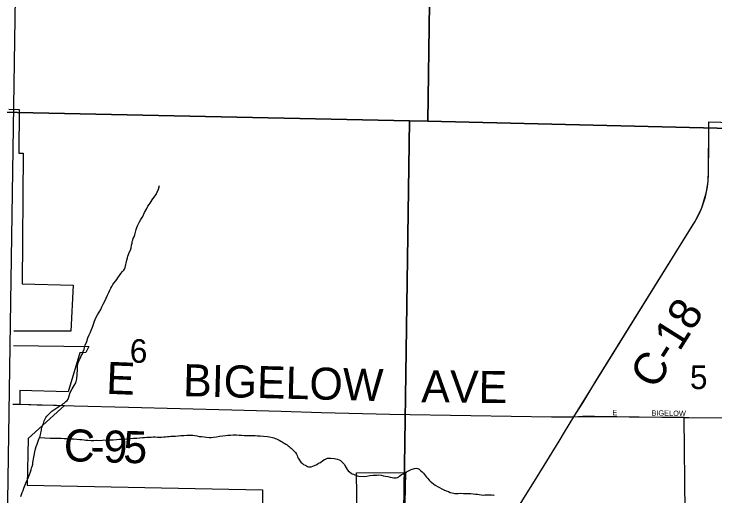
# Model space of a CAD drawing. Extents: x 1587405 to 1714697, y 1028970 to 1155083.
# Drawn here: x 1652641 to 1659199, y 1120584 to 1125096 of the extents above; entities that cross this region are included whole.
import ezdxf

# ---------------------------------------------------------------- set-up
doc = ezdxf.new("R2010")
doc.units = 0
for name, color, linetype in [('GM_X_City_Street', 7, 'Continuous'), ('GM_X_City_Street_Text', 7, 'Continuous'), ('GM_X_Corporation', 7, 'Continuous'), ('GM_X_County_Road', 7, 'Continuous'), ('GM_X_County_Road_Text', 7, 'Continuous'), ('GM_X_Minor_River', 7, 'Continuous'), ('GM_X_Rail_Line', 7, 'Continuous'), ('GM_X_Section', 7, 'Continuous'), ('GM_X_Section_Text', 7, 'Continuous')]:
    doc.layers.add(name, color=color, linetype=linetype)

msp = doc.modelspace()

# ---------------------------------------------------------------- linework, layer by layer
at = {"layer": 'GM_X_City_Street'}
for points in [[(1652630.5, 1121444.8), (1652694.2, 1121443.7)], [(1657877.7, 1121326.3), (1657959.4, 1121330.9), (1658004.6, 1121332.2), (1658071.3, 1121331.8), (1658909.3, 1121318.3)], [(1658909.3, 1121318.3), (1658955.7, 1121317.5), (1659332.4, 1121314.8), (1659921.8, 1121300.5), (1660298.6, 1121295.1), (1660354.3, 1121294.3)]]:
    msp.add_lwpolyline(points, dxfattribs=at)
at = {"layer": 'GM_X_Corporation'}
for points in [[(1652592, 1124205), (1652690.2, 1124200.8), (1652687.2, 1123791.5), (1652725.8, 1123791.5), (1652716.6, 1122570.3), (1653196.1, 1122558.6), (1653173.1, 1122125.9), (1652638.6, 1122126.2)], [(1658937.7, 1118659.7), (1658909.3, 1121318.3), (1657877.6, 1121326.3), (1659011.7, 1123151.3), (1659077, 1123282.1), (1659120.9, 1123430.8), (1659135, 1123527.3), (1659137.3, 1123597.9), (1659142.1, 1124087.2), (1660138.3, 1124058.6)], [(1652636.4, 1121991.9), (1653340.5, 1121983.2), (1653312.4, 1121926.9), (1653256.9, 1121924.1), (1653147.7, 1121558.6), (1652696, 1121572.7), (1652694.2, 1121443.7), (1653113.7, 1121430.9), (1652774.2, 1121120.9), (1652763.2, 1120685.9), (1654964.8, 1120642.1), (1654964.7, 1120391.2)], [(1655850.7, 1120385.1), (1655846.4, 1120801.7), (1656304.6, 1120803.9), (1656274.1, 1119387)]]:
    msp.add_lwpolyline(points, dxfattribs=at)
at = {"layer": 'GM_X_County_Road'}
for points in [[(1657877.7, 1121326.3), (1657961.7, 1121456.5), (1658084.7, 1121657.4), (1658447.7, 1122240.9), (1658930.7, 1123019.5), (1659008, 1123144.8), (1659040.2, 1123201.5), (1659061.8, 1123245.2), (1659080.4, 1123290.2), (1659096.3, 1123336.4), (1659109.9, 1123383.3), (1659120.9, 1123430.8), (1659129.1, 1123478.9), (1659135, 1123527.3), (1659136.7, 1123561.1), (1659137.3, 1123597.9), (1659139.1, 1123680.9), (1659140.8, 1123811.2), (1659142.9, 1123992.6), (1659142.1, 1124087.2)], [(1652694.2, 1121443.7), (1652857.9, 1121438.2), (1653038.6, 1121433.4), (1653113.7, 1121430.9)], [(1653113.7, 1121430.9), (1653202.6, 1121428.1), (1653711.6, 1121414.1), (1654680.3, 1121389.6), (1655140.1, 1121377.7), (1655517.5, 1121366.6), (1656158, 1121350.4), (1656913.4, 1121336.2), (1657669, 1121324.9), (1657793.5, 1121323.8), (1657877.7, 1121326.3)], [(1656896.3, 1119728.3), (1657089, 1120038), (1657268.5, 1120331.6), (1657535, 1120763.9), (1657741.7, 1121098.3), (1657792.5, 1121182.6), (1657877.7, 1121326.3)]]:
    msp.add_lwpolyline(points, dxfattribs=at)
at = {"layer": 'GM_X_Minor_River'}
for points in [[(1652949.7, 1121331.1), (1652962, 1121342.8), (1652972.3, 1121354.7), (1652982.5, 1121366.5), (1652994.8, 1121378.3), (1653015.2, 1121391.9), (1653033.5, 1121403.6), (1653049.8, 1121415.3), (1653064, 1121425), (1653078.2, 1121430.8), (1653088.4, 1121438.6), (1653098.6, 1121446.4), (1653110.8, 1121454.2), (1653125.1, 1121469.9), (1653137.3, 1121477.7), (1653147.6, 1121489.5), (1653167, 1121553.3), (1653183.7, 1121587.1), (1653202.4, 1121616.8), (1653219, 1121642.5), (1653227.8, 1121680.5), (1653232.6, 1121720.5), (1653235.6, 1121768.6), (1653236.2, 1121800.6), (1653238.6, 1121818.7), (1653242.9, 1121830.6), (1653247.2, 1121844.6), (1653253.5, 1121860.5), (1653261.9, 1121878.4), (1653270.3, 1121896.2), (1653280.7, 1121916.1), (1653289.2, 1121936), (1653297.7, 1121957.9), (1653306.5, 1121995.8), (1653321.2, 1122029.6), (1653331.9, 1122063.5), (1653344.6, 1122093.3), (1653357.1, 1122117.1), (1653365.6, 1122141.1), (1653376.1, 1122164.9), (1653384.7, 1122192.8), (1653395.3, 1122220.7), (1653408, 1122250.5), (1653422.6, 1122278.3), (1653437.2, 1122304.1), (1653453.8, 1122329.8), (1653464.3, 1122353.7), (1653476.8, 1122379.5), (1653489.5, 1122407.3), (1653504.1, 1122435.1), (1653514.7, 1122463), (1653527.2, 1122488.8), (1653537.7, 1122510.7), (1653546.1, 1122528.6), (1653556.5, 1122544.4), (1653566.9, 1122562.2), (1653577.3, 1122580.1), (1653589.6, 1122593.9), (1653601.9, 1122609.7), (1653612.3, 1122627.5), (1653626.8, 1122647.3), (1653641.2, 1122667.1), (1653655.7, 1122684.8), (1653668, 1122698.6), (1653676.2, 1122708.5), (1653682.5, 1122722.4), (1653697.9, 1122790.3), (1653702.4, 1122812.3), (1653706.7, 1122828.2), (1653711.1, 1122844.2), (1653719.5, 1122864.1), (1653730, 1122885.9), (1653736.5, 1122907.8), (1653741, 1122931.8), (1653745.3, 1122949.8), (1653747.7, 1122965.8), (1653751.9, 1122977.7), (1653756.3, 1122995.7), (1653764.6, 1123009.6), (1653771.1, 1123029.5), (1653777.6, 1123053.5), (1653784.1, 1123079.4), (1653790.5, 1123097.3), (1653796.8, 1123113.2), (1653805.2, 1123131.1), (1653815.6, 1123149), (1653828.1, 1123172.8), (1653844.8, 1123200.6), (1653861.6, 1123236.3), (1653882.4, 1123274), (1653892.9, 1123297.9), (1653905.3, 1123313.7), (1653913.5, 1123325.5), (1653923.9, 1123339.4), (1653934.2, 1123355.2), (1653948.7, 1123377), (1653963.1, 1123394.7), (1653973.5, 1123412.6), (1653981.9, 1123428.5), (1653992.5, 1123456.3), (1654001.2, 1123490.3)], [(1652705.6, 1120579.8), (1652711.9, 1120597.7), (1652718.4, 1120617.6), (1652726.8, 1120635.5), (1652733.2, 1120657.4), (1652745.9, 1120687.3), (1652756.4, 1120713.1), (1652767, 1120737), (1652775.5, 1120760.9), (1652786, 1120784.8), (1652794.5, 1120808.7), (1652801, 1120828.6), (1652805.3, 1120846.6), (1652809.6, 1120860.5), (1652816.1, 1120880.4), (1652818.4, 1120898.4), (1652820.7, 1120912.4), (1652823.1, 1120930.4), (1652829.8, 1120962.4), (1652836.5, 1120996.4), (1652843.1, 1121024.3), (1652849.6, 1121048.2), (1652858.1, 1121070.1), (1652864.5, 1121088.1), (1652870.9, 1121106), (1652879.4, 1121129.9), (1652885.7, 1121143.8), (1652890, 1121157.7), (1652892.3, 1121173.8), (1652894.6, 1121187.8), (1652896.9, 1121199.7), (1652899.1, 1121211.7), (1652901.4, 1121223.7), (1652905.6, 1121233.7), (1652909.9, 1121247.6), (1652916.2, 1121261.5), (1652920.5, 1121275.5), (1652924.7, 1121287.4), (1652931, 1121301.3), (1652939.4, 1121317.2), (1652949.7, 1121331.1)], [(1652879.4, 1121129.9), (1652979.6, 1121125.8), (1652993.7, 1121125.6), (1653009.7, 1121125.2), (1653023.8, 1121125), (1653039.8, 1121126.6), (1653061.9, 1121126.2), (1653081.9, 1121123.8), (1653110, 1121123.2), (1653132.1, 1121122.8), (1653154.1, 1121120.3), (1653176.2, 1121119.9), (1653196.2, 1121117.5), (1653258.3, 1121114.2), (1653276.3, 1121111.8), (1653296.4, 1121109.4), (1653312.4, 1121107.1), (1653332.4, 1121106.7), (1653362.5, 1121104.1), (1653386.5, 1121103.6), (1653410.7, 1121105.1), (1653438.7, 1121104.6), (1653468.9, 1121105.9), (1653503, 1121109.3), (1653535.2, 1121110.6), (1653567.3, 1121110), (1653599.4, 1121111.3), (1653627.6, 1121114.8), (1653655.7, 1121116.2), (1653695.9, 1121119.4), (1653728.1, 1121122.8), (1653760.2, 1121124.1), (1653790.3, 1121125.5), (1653818.5, 1121127), (1653842.6, 1121130.5), (1653862.7, 1121132.1), (1653884.8, 1121133.7), (1653906.9, 1121135.2), (1653925, 1121134.9), (1653943.1, 1121136.5), (1653961.1, 1121136.1), (1653983.2, 1121135.7), (1653999.3, 1121135.4), (1654021.3, 1121134.9), (1654041.4, 1121136.5), (1654057.5, 1121138.2), (1654075.6, 1121139.8), (1654093.7, 1121141.5), (1654109.8, 1121143.2), (1654125.9, 1121144.8), (1654137.9, 1121144.6), (1654152, 1121144.3), (1654178.1, 1121145.8), (1654202.2, 1121149.3), (1654230.3, 1121150.8), (1654256.5, 1121152.2), (1654276.6, 1121153.8), (1654296.6, 1121153.4), (1654314.7, 1121153.1), (1654332.7, 1121150.7), (1654352.7, 1121146.3), (1654374.6, 1121141.8), (1654396.7, 1121139.4), (1654466.7, 1121129.9), (1654486.8, 1121131.6), (1654509, 1121135.1), (1654535.1, 1121138.6), (1654563.3, 1121144.1), (1654593.5, 1121147.4), (1654619.7, 1121150.9), (1654641.8, 1121152.5), (1654665.9, 1121154), (1654692, 1121155.5), (1654722.1, 1121154.9), (1654746.2, 1121154.4), (1654770.2, 1121151.9), (1654794.3, 1121151.4), (1654816.3, 1121151), (1654838.4, 1121150.5), (1654858.4, 1121150.1), (1654878.5, 1121149.7), (1654896.6, 1121149.4), (1654920.6, 1121146.9), (1654944.7, 1121146.4), (1654976.7, 1121143.7), (1655012.8, 1121141), (1655030.7, 1121136.6), (1655058.7, 1121130.1), (1655072.7, 1121127.8), (1655084.7, 1121123.5), (1655096.6, 1121119.2), (1655108.5, 1121113), (1655120.4, 1121106.7), (1655136.3, 1121098.4), (1655150.2, 1121090.1), (1655170, 1121077.6), (1655183.9, 1121069.3), (1655195.8, 1121063.1), (1655205.7, 1121054.9), (1655215.5, 1121046.6), (1655225.4, 1121038.4)], [(1655225.4, 1121038.4), (1655235.3, 1121030.2), (1655252.9, 1121011.8), (1655264.7, 1120999.5), (1655274.6, 1120991.3), (1655284.3, 1120975.1), (1655290.1, 1120962.9), (1655293.8, 1120950.8), (1655299.6, 1120938.6), (1655305.4, 1120928.5), (1655324.9, 1120900), (1655340.7, 1120887.7), (1655350.6, 1120879.4), (1655364.4, 1120871.1), (1655376.4, 1120864.9), (1655386.3, 1120858.7), (1655396.3, 1120856.5), (1655412.3, 1120856.1), (1655422.4, 1120857.9), (1655436.5, 1120861.7), (1655452.7, 1120869.4), (1655473, 1120879), (1655491.3, 1120890.7), (1655509.4, 1120896.3), (1655529.9, 1120915.9), (1655546.2, 1120925.6), (1655556.3, 1120929.5), (1655572.5, 1120937.1), (1655588.6, 1120938.8), (1655606.6, 1120938.5), (1655636.6, 1120933.9), (1655668.6, 1120927.2), (1655684.5, 1120920.9), (1655694.4, 1120914.6), (1655704.3, 1120906.4), (1655714.2, 1120898.2), (1655724, 1120888), (1655731.8, 1120877.8), (1655739.6, 1120863.6), (1655749.3, 1120847.3), (1655759, 1120833.1), (1655766.8, 1120820.9), (1655780.6, 1120808.6), (1655794.4, 1120798.3), (1655806.3, 1120792), (1655816.3, 1120787.8), (1655828.2, 1120781.6), (1655838.1, 1120777.3), (1655852.1, 1120773.1), (1655866.1, 1120770.8), (1655922.2, 1120767.6), (1655942.3, 1120769.2), (1655968.5, 1120774.7), (1656000.7, 1120780.1), (1656034.8, 1120779.4), (1656054.9, 1120781), (1656074.9, 1120778.6), (1656096.9, 1120774.1), (1656116.9, 1120769.7), (1656136.9, 1120765.3), (1656160.9, 1120760.8), (1656178.8, 1120756.4), (1656194.8, 1120754.1), (1656204.9, 1120753.9), (1656216.9, 1120753.7), (1656229, 1120755.4), (1656241.2, 1120763.2), (1656251.4, 1120773), (1656267.7, 1120784.7), (1656283.9, 1120792.4), (1656300.2, 1120802.1), (1656314.4, 1120809.9), (1656326.6, 1120817.6), (1656338.7, 1120823.4), (1656350.9, 1120829.2), (1656365.1, 1120834.9), (1656377.2, 1120838.7), (1656387.3, 1120840.5), (1656405.4, 1120844.1), (1656419.4, 1120841.8), (1656431.3, 1120833.6), (1656445.1, 1120823.3), (1656458.9, 1120811), (1656470.7, 1120798.7), (1656480.5, 1120786.5), (1656490.2, 1120772.2), (1656500, 1120760), (1656511.8, 1120747.7), (1656525.5, 1120733.4), (1656535.4, 1120723.2), (1656549.1, 1120710.9), (1656564.9, 1120696.5), (1656582.7, 1120684.1), (1656602.5, 1120671.7), (1656662.1, 1120642.4), (1656684, 1120631.9), (1656705.9, 1120625.5), (1656721.8, 1120617.1), (1656741.8, 1120612.7), (1656753.8, 1120610.4), (1656763.8, 1120608.2)], [(1656763.8, 1120608.2), (1656779.8, 1120605.9), (1656797.9, 1120607.6), (1656822, 1120609.1), (1656846.1, 1120608.6), (1656868.1, 1120608.2), (1656892.2, 1120607.7), (1656914.3, 1120607.2), (1656936.3, 1120604.8), (1656958.3, 1120602.3), (1656968.3, 1120602.1), (1656978.3, 1120599.9), (1656992.3, 1120597.6), (1657012.3, 1120595.2), (1657030.4, 1120592.8), (1657046.4, 1120594.5), (1657058.5, 1120594.3), (1657084.6, 1120593.8), (1657108.6, 1120593.3), (1657128.7, 1120592.9), (1657132.7, 1120592.8), (1657130.7, 1120592.8)]]:
    msp.add_lwpolyline(points, dxfattribs=at)
at = {"layer": 'GM_X_Rail_Line'}
msp.add_lwpolyline([(1652548.3, 1112173.7), (1652519.2, 1112269.3), (1652498.2, 1112347.5), (1652483.9, 1112418), (1652474.2, 1112487.5), (1652465.5, 1112570.8), (1652461.4, 1112683.8), (1652464.5, 1112910.7), (1652504.7, 1115460.5), (1652527.4, 1116926.5), (1652548.1, 1118268.2), (1652590, 1120951.9), (1652611.9, 1122399.8), (1652652.7, 1125050.4), (1652715.2, 1129083.1), (1652745.5, 1130967.3), (1652787, 1134322.7)], dxfattribs=at)
at = {"layer": 'GM_X_Section'}
for points in [[(1651430.8, 1129477.7), (1656587, 1129382.1), (1656513.6, 1124091.6), (1656339.6, 1124095.9), (1651349.7, 1124201.4)], [(1656587, 1129382.1), (1661871, 1129232.6), (1661797.4, 1123966), (1656513.6, 1124091.6)], [(1656339.6, 1124095.9), (1656263, 1118717.5), (1651255.5, 1118849.2), (1651252.7, 1118939.3), (1651349.7, 1124201.4)], [(1656513.6, 1124091.6), (1661797.4, 1123966), (1661837.5, 1123967.6), (1661639.2, 1118644.5), (1656263, 1118717.5), (1656339.6, 1124095.9)]]:
    msp.add_lwpolyline(points, close=True, dxfattribs=at)

# ---------------------------------------------------------------- texts
at = {"layer": 'GM_X_City_Street_Text'}
for s, rotation, p in [('E', 0.00001, (1658238.8, 1121340.2)), ('BIGELOW', 359.22622, (1658604.1, 1121335.9))]:
    msp.add_text(s, height=50, rotation=rotation, dxfattribs=at).set_placement(p)
at = {"layer": 'GM_X_County_Road_Text'}
for s, rotation, p in [('C-18', 57.92331, (1658641.6, 1121570.1)), ('E', 357.75543, (1653500.2, 1121541.1)), ('BIGELOW', 358.54636, (1654220.5, 1121519.2)), ('AVE', 359.33215, (1656450.8, 1121462.1)), ('C', 357.8529, (1653102.4, 1120911.8)), ('9', 358.47283, (1653475.4, 1120899.1)), ('5', 358.49268, (1653660.2, 1120894.2)), ('-', 358.41494, (1653351.9, 1120902.5))]:
    msp.add_text(s, height=300, rotation=rotation, dxfattribs=at).set_placement(p)
at = {"layer": 'GM_X_Section_Text'}
for s, p in [('6', (1653724.4, 1121830.6)), ('5', (1658964.8, 1121584.7))]:
    msp.add_text(s, height=221, rotation=0.00001, dxfattribs=at).set_placement(p)

doc.saveas('drawing.dxf')
